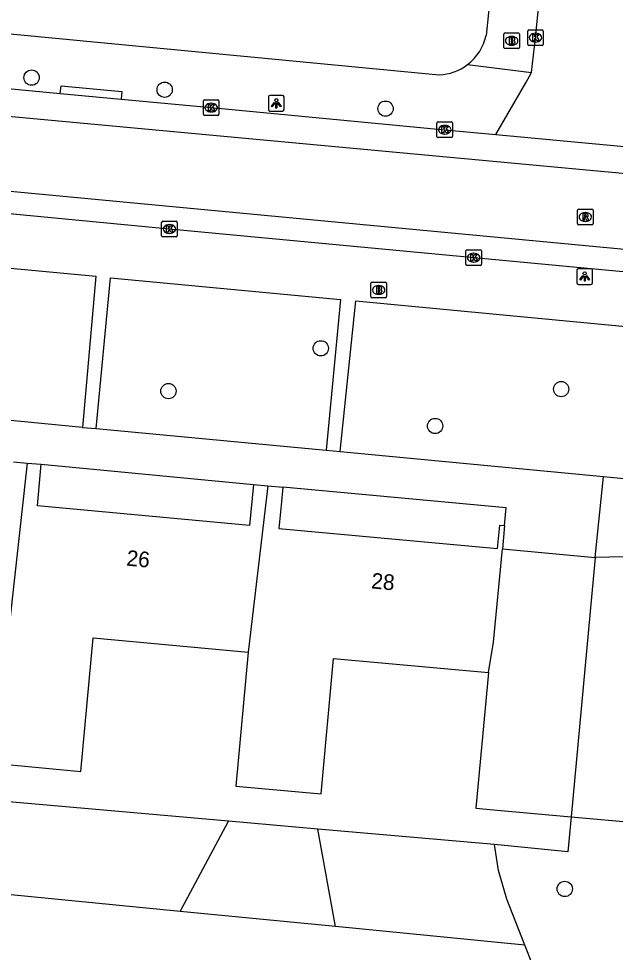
# Model space of a CAD drawing. Extents: x 162186 to 163152, y 385513 to 386513.
# Drawn here: x 162291.8 to 162330, y 385675.7 to 385735.4 of the extents above; entities that cross this region are included whole.
import ezdxf

# ---------------------------------------------------------------- set-up
doc = ezdxf.new("R2010")
doc.units = 0
for name, color, linetype in [('IMGEO_Boom', 7, 'Continuous'), ('IMGEO_Brandkraan', 7, 'Continuous'), ('IMGEO_Groenvoorziening', 7, 'Continuous'), ('IMGEO_Kolk', 7, 'Continuous'), ('IMGEO_Lichtpunt', 7, 'Continuous'), ('IMGEO_Pand', 7, 'Continuous'), ('IMGEO_Pand_nummerreeks', 7, 'Continuous'), ('IMGEO_Rijbaan_lokaal_gesloten', 7, 'Continuous'), ('IMGEO_Rijbaan_lokaal_open', 7, 'Continuous'), ('IMGEO_Rioolput', 7, 'Continuous'), ('IMGEO_Voetpad_open', 7, 'Continuous')]:
    doc.layers.add(name, color=color, linetype=linetype)

msp = doc.modelspace()

# ---------------------------------------------------------------- linework, layer by layer
at = {"layer": 'IMGEO_Boom'}
for centre in [(162292.628, 385731.676), (162301.15, 385730.904), (162315.298, 385729.691), (162311.147, 385714.353), (162326.546, 385711.742), (162301.394, 385711.615), (162318.473, 385709.382), (162326.774, 385679.752)]:
    msp.add_circle(centre, 0.489, dxfattribs=at)
at = {"layer": 'IMGEO_Brandkraan'}
for p, q in [((162322.878, 385733.607), (162322.878, 385734.459)), ((162322.953, 385734.533), (162323.805, 385734.533)), ((162323.366, 385734.313), (162323.391, 385734.313)), ((162323.879, 385734.459), (162323.879, 385733.607)), ((162323.389, 385733.753), (162323.364, 385733.753)), ((162323.805, 385733.533), (162322.953, 385733.533)), ((162314.361, 385717.663), (162314.361, 385718.515)), ((162314.436, 385718.589), (162315.288, 385718.589)), ((162314.849, 385718.369), (162314.874, 385718.369)), ((162315.362, 385718.515), (162315.362, 385717.663)), ((162315.288, 385717.589), (162314.436, 385717.589)), ((162314.872, 385717.809), (162314.847, 385717.809))]:
    msp.add_line(p, q, dxfattribs=at)
for points in [[(162322.878, 385733.607), (162322.878, 385734.459)], [(162322.953, 385734.533), (162323.805, 385734.533)], [(162323.879, 385734.459), (162323.879, 385733.607)], [(162323.226, 385734.233), (162323.226, 385733.833), (162323.439, 385733.833)], [(162323.457, 385734.233), (162323.226, 385734.233)], [(162323.405, 385734.152), (162323.351, 385734.152), (162323.351, 385734.076)], [(162323.351, 385734.076), (162323.404, 385734.076)], [(162323.413, 385734), (162323.351, 385734), (162323.351, 385733.919)], [(162323.351, 385733.919), (162323.413, 385733.919)], [(162323.805, 385733.533), (162322.953, 385733.533)], [(162314.361, 385717.663), (162314.361, 385718.515)], [(162314.436, 385718.589), (162315.288, 385718.589)], [(162314.709, 385718.289), (162314.709, 385717.889), (162314.922, 385717.889)], [(162314.94, 385718.289), (162314.709, 385718.289)], [(162314.888, 385718.208), (162314.834, 385718.208), (162314.834, 385718.132)], [(162315.362, 385718.515), (162315.362, 385717.663)], [(162315.288, 385717.589), (162314.436, 385717.589)], [(162314.834, 385718.132), (162314.887, 385718.132)], [(162314.896, 385718.056), (162314.834, 385718.056), (162314.834, 385717.975)], [(162314.834, 385717.975), (162314.896, 385717.975)]]:
    msp.add_lwpolyline(points, dxfattribs=at)
for centre, radius, start, end in [((162322.955, 385734.457), 0.0765, 91.55205, 178.44795), ((162322.955, 385734.457), 0.0765, 91.55205, 178.44795), ((162323.803, 385734.457), 0.0765, 1.55205, 88.44795), ((162323.803, 385734.457), 0.0765, 1.55205, 88.44795), ((162323.406, 385734.114), 0.0379, 267.82845, 90.93552), ((162323.414, 385733.959), 0.0404, 269.87594, 90.50774), ((162323.445, 385734.084), 0.251, 268.66757, 293.53466), ((162323.461, 385734.088), 0.145, 59.4692, 91.53667), ((162323.486, 385734.135), 0.0922, 285.51372, 58.15012), ((162323.491, 385733.943), 0.105, 301.31148, 78.98903), ((162322.955, 385733.609), 0.0765, 181.55205, 268.44795), ((162322.955, 385733.609), 0.0765, 181.55205, 268.44795), ((162323.803, 385733.609), 0.0765, 271.55205, 358.44795), ((162323.803, 385733.609), 0.0765, 271.55205, 358.44795), ((162314.438, 385718.513), 0.0765, 91.55205, 178.44795), ((162314.438, 385718.513), 0.0765, 91.55205, 178.44795), ((162314.889, 385718.17), 0.0379, 267.82845, 90.93552), ((162314.944, 385718.144), 0.145, 59.4692, 91.53667), ((162314.969, 385718.191), 0.0922, 285.51372, 58.15012), ((162315.286, 385718.513), 0.0765, 1.55205, 88.44795), ((162315.286, 385718.513), 0.0765, 1.55205, 88.44795), ((162314.438, 385717.665), 0.0765, 181.55205, 268.44795), ((162314.438, 385717.665), 0.0765, 181.55205, 268.44795), ((162314.897, 385718.015), 0.0404, 269.87594, 90.50774), ((162314.928, 385718.14), 0.251, 268.66757, 293.53466), ((162314.974, 385717.999), 0.105, 301.31148, 78.98903), ((162315.286, 385717.665), 0.0765, 271.55205, 358.44795), ((162315.286, 385717.665), 0.0765, 271.55205, 358.44795)]:
    msp.add_arc(centre, radius, start, end, dxfattribs=at)
for centre, major_axis, ratio, start_param, end_param in [((162323.365, 385734.033), (-0.387, 0.002), 0.722429, 4.712389, 7.853982), ((162323.39, 385734.033), (-0.39, 0.002), 0.717154, 1.570796, 4.712389), ((162314.848, 385718.089), (-0.387, 0.002), 0.722429, 4.712389, 7.853982), ((162314.873, 385718.089), (-0.39, 0.002), 0.717154, 1.570796, 4.712389)]:
    msp.add_ellipse(centre, major_axis=major_axis, ratio=ratio, start_param=start_param, end_param=end_param, dxfattribs=at)
at = {"layer": 'IMGEO_Groenvoorziening'}
for points in [[(162336.141, 385703.282), (162337.233, 385702.638), (162338.466, 385701.56), (162339.344, 385699.923), (162340.593, 385695.492), (162341.243, 385692.652), (162341.563, 385691.252), (162343.641, 385684.905), (162344.138, 385682.696), (162344.331, 385681.045), (162344.168, 385679.279), (162343.181, 385676.687), (162341.102, 385673.713), (162338.464, 385671.335), (162335.609, 385669.807), (162333.743, 385669.347), (162331.47, 385669.611), (162329.323, 385670.65), (162327.366, 385671.752), (162325.625, 385673.388), (162324.721, 385674.923), (162324.229, 385676.165)], [(162305.235, 385684.094), (162289.198, 385685.507)], [(162302.141, 385678.318), (162305.235, 385684.094)], [(162310.963, 385683.589), (162305.235, 385684.094)], [(162327.188, 385684.362), (162326.973, 385682.13), (162322.266, 385682.593)], [(162312.094, 385677.348), (162310.963, 385683.589)], [(162322.266, 385682.593), (162310.963, 385683.589)], [(162324.229, 385676.165), (162323.066, 385679.099), (162322.53, 385680.94), (162322.266, 385682.593)], [(162302.141, 385678.318), (162289.75, 385679.525)], [(162312.094, 385677.348), (162302.141, 385678.318)], [(162324.229, 385676.165), (162312.094, 385677.348)]]:
    msp.add_lwpolyline(points, dxfattribs=at)
at = {"layer": 'IMGEO_Kolk'}
for p, q in [((162324.403, 385733.806), (162324.403, 385734.658)), ((162324.478, 385734.732), (162325.33, 385734.732)), ((162324.891, 385734.512), (162324.916, 385734.512)), ((162325.404, 385734.658), (162325.404, 385733.806)), ((162325.33, 385733.732), (162324.478, 385733.732)), ((162324.914, 385733.952), (162324.889, 385733.952)), ((162303.629, 385729.334), (162303.629, 385730.186)), ((162303.704, 385730.26), (162304.556, 385730.26)), ((162304.63, 385730.186), (162304.63, 385729.334)), ((162304.117, 385730.04), (162304.142, 385730.04)), ((162304.556, 385729.26), (162303.704, 385729.26)), ((162304.14, 385729.48), (162304.115, 385729.48)), ((162318.592, 385727.914), (162318.592, 385728.766)), ((162318.667, 385728.84), (162319.519, 385728.84)), ((162319.08, 385728.62), (162319.105, 385728.62)), ((162319.593, 385728.766), (162319.593, 385727.914)), ((162319.519, 385727.84), (162318.667, 385727.84)), ((162319.103, 385728.06), (162319.078, 385728.06)), ((162300.957, 385721.561), (162300.957, 385722.413)), ((162301.032, 385722.487), (162301.884, 385722.487)), ((162301.958, 385722.413), (162301.958, 385721.561)), ((162301.445, 385722.267), (162301.47, 385722.267)), ((162301.884, 385721.487), (162301.032, 385721.487)), ((162301.468, 385721.707), (162301.443, 385721.707)), ((162320.441, 385719.729), (162320.441, 385720.581)), ((162320.516, 385720.655), (162321.368, 385720.655)), ((162321.442, 385720.581), (162321.442, 385719.729)), ((162320.929, 385720.435), (162320.954, 385720.435)), ((162321.368, 385719.655), (162320.516, 385719.655)), ((162320.952, 385719.875), (162320.927, 385719.875))]:
    msp.add_line(p, q, dxfattribs=at)
for points in [[(162324.403, 385733.806), (162324.403, 385734.658)], [(162324.478, 385734.732), (162325.33, 385734.732)], [(162324.724, 385734.432), (162324.847, 385734.432), (162324.847, 385734.281), (162324.977, 385734.432), (162325.141, 385734.432), (162324.995, 385734.281), (162325.148, 385734.032), (162324.996, 385734.032), (162324.911, 385734.196), (162324.847, 385734.129), (162324.847, 385734.032), (162324.724, 385734.032), (162324.724, 385734.432)], [(162325.404, 385734.658), (162325.404, 385733.806)], [(162325.33, 385733.732), (162324.478, 385733.732)], [(162303.629, 385729.334), (162303.629, 385730.186)], [(162303.704, 385730.26), (162304.556, 385730.26)], [(162304.63, 385730.186), (162304.63, 385729.334)], [(162303.95, 385729.96), (162304.073, 385729.96), (162304.073, 385729.809), (162304.203, 385729.96), (162304.367, 385729.96), (162304.221, 385729.809), (162304.374, 385729.56), (162304.222, 385729.56), (162304.137, 385729.724), (162304.073, 385729.657), (162304.073, 385729.56), (162303.95, 385729.56), (162303.95, 385729.96)], [(162304.556, 385729.26), (162303.704, 385729.26)], [(162318.592, 385727.914), (162318.592, 385728.766)], [(162318.667, 385728.84), (162319.519, 385728.84)], [(162318.913, 385728.54), (162319.036, 385728.54), (162319.036, 385728.389), (162319.166, 385728.54), (162319.33, 385728.54), (162319.184, 385728.389), (162319.337, 385728.14), (162319.185, 385728.14), (162319.1, 385728.304), (162319.036, 385728.237), (162319.036, 385728.14), (162318.913, 385728.14), (162318.913, 385728.54)], [(162319.593, 385728.766), (162319.593, 385727.914)], [(162319.519, 385727.84), (162318.667, 385727.84)], [(162300.957, 385721.561), (162300.957, 385722.413)], [(162301.032, 385722.487), (162301.884, 385722.487)], [(162301.958, 385722.413), (162301.958, 385721.561)], [(162301.278, 385722.187), (162301.401, 385722.187), (162301.401, 385722.036), (162301.531, 385722.187), (162301.695, 385722.187), (162301.549, 385722.036), (162301.702, 385721.787), (162301.55, 385721.787), (162301.465, 385721.951), (162301.401, 385721.884), (162301.401, 385721.787), (162301.278, 385721.787), (162301.278, 385722.187)], [(162301.884, 385721.487), (162301.032, 385721.487)], [(162320.441, 385719.729), (162320.441, 385720.581)], [(162320.516, 385720.655), (162321.368, 385720.655)], [(162321.442, 385720.581), (162321.442, 385719.729)], [(162320.762, 385720.355), (162320.885, 385720.355), (162320.885, 385720.204), (162321.015, 385720.355), (162321.179, 385720.355), (162321.033, 385720.204), (162321.186, 385719.955), (162321.034, 385719.955), (162320.949, 385720.119), (162320.885, 385720.052), (162320.885, 385719.955), (162320.762, 385719.955), (162320.762, 385720.355)], [(162321.368, 385719.655), (162320.516, 385719.655)]]:
    msp.add_lwpolyline(points, dxfattribs=at)
for centre, start, end in [((162324.48, 385734.656), 91.55205, 178.44795), ((162324.48, 385734.656), 91.55205, 178.44795), ((162325.328, 385734.656), 1.55205, 88.44795), ((162325.328, 385734.656), 1.55205, 88.44795), ((162324.48, 385733.808), 181.55205, 268.44795), ((162324.48, 385733.808), 181.55205, 268.44795), ((162325.328, 385733.808), 271.55205, 358.44795), ((162325.328, 385733.808), 271.55205, 358.44795), ((162303.706, 385730.184), 91.55205, 178.44795), ((162303.706, 385730.184), 91.55205, 178.44795), ((162304.554, 385730.184), 1.55205, 88.44795), ((162304.554, 385730.184), 1.55205, 88.44795), ((162303.706, 385729.336), 181.55205, 268.44795), ((162303.706, 385729.336), 181.55205, 268.44795), ((162304.554, 385729.336), 271.55205, 358.44795), ((162304.554, 385729.336), 271.55205, 358.44795), ((162318.669, 385728.764), 91.55205, 178.44795), ((162318.669, 385728.764), 91.55205, 178.44795), ((162319.517, 385728.764), 1.55205, 88.44795), ((162319.517, 385728.764), 1.55205, 88.44795), ((162318.669, 385727.916), 181.55205, 268.44795), ((162318.669, 385727.916), 181.55205, 268.44795), ((162319.517, 385727.916), 271.55205, 358.44795), ((162319.517, 385727.916), 271.55205, 358.44795), ((162301.034, 385722.411), 91.55205, 178.44795), ((162301.034, 385722.411), 91.55205, 178.44795), ((162301.882, 385722.411), 1.55205, 88.44795), ((162301.882, 385722.411), 1.55205, 88.44795), ((162301.034, 385721.563), 181.55205, 268.44795), ((162301.034, 385721.563), 181.55205, 268.44795), ((162301.882, 385721.563), 271.55205, 358.44795), ((162301.882, 385721.563), 271.55205, 358.44795), ((162320.518, 385720.579), 91.55205, 178.44795), ((162320.518, 385720.579), 91.55205, 178.44795), ((162321.366, 385720.579), 1.55205, 88.44795), ((162321.366, 385720.579), 1.55205, 88.44795), ((162320.518, 385719.731), 181.55205, 268.44795), ((162320.518, 385719.731), 181.55205, 268.44795), ((162321.366, 385719.731), 271.55205, 358.44795), ((162321.366, 385719.731), 271.55205, 358.44795)]:
    msp.add_arc(centre, 0.0765, start, end, dxfattribs=at)
for centre, major_axis, ratio, start_param, end_param in [((162324.89, 385734.232), (-0.387, 0.002), 0.722429, 4.712389, 7.853982), ((162324.915, 385734.232), (-0.39, 0.002), 0.717154, 1.570796, 4.712389), ((162304.116, 385729.76), (-0.387, 0.002), 0.722429, 4.712389, 7.853982), ((162304.141, 385729.76), (-0.39, 0.002), 0.717154, 1.570796, 4.712389), ((162319.079, 385728.34), (-0.387, 0.002), 0.722429, 4.712389, 7.853982), ((162319.104, 385728.34), (-0.39, 0.002), 0.717154, 1.570796, 4.712389), ((162301.444, 385721.987), (-0.387, 0.002), 0.722429, 4.712389, 7.853982), ((162301.469, 385721.987), (-0.39, 0.002), 0.717154, 1.570796, 4.712389), ((162320.928, 385720.155), (-0.387, 0.002), 0.722429, 4.712389, 7.853982), ((162320.953, 385720.155), (-0.39, 0.002), 0.717154, 1.570796, 4.712389)]:
    msp.add_ellipse(centre, major_axis=major_axis, ratio=ratio, start_param=start_param, end_param=end_param, dxfattribs=at)
at = {"layer": 'IMGEO_Lichtpunt'}
for p, q in [((162307.802, 385730.437), (162307.802, 385729.63)), ((162307.802, 385730.437), (162307.802, 385729.63)), ((162308.704, 385730.532), (162307.896, 385730.532)), ((162308.704, 385730.532), (162307.896, 385730.532)), ((162308.798, 385729.63), (162308.798, 385730.437)), ((162308.798, 385729.63), (162308.798, 385730.437)), ((162307.896, 385729.536), (162308.704, 385729.536)), ((162307.896, 385729.536), (162308.704, 385729.536)), ((162327.555, 385719.348), (162327.555, 385718.541)), ((162327.555, 385719.348), (162327.555, 385718.541)), ((162328.457, 385719.443), (162327.649, 385719.443)), ((162328.457, 385719.443), (162327.649, 385719.443)), ((162328.551, 385718.541), (162328.551, 385719.348)), ((162328.551, 385718.541), (162328.551, 385719.348)), ((162327.649, 385718.447), (162328.457, 385718.447)), ((162327.649, 385718.447), (162328.457, 385718.447))]:
    msp.add_line(p, q, dxfattribs=at)
for points in [[(162308.176, 385730.101), (162308.215, 385730.073), (162308.027, 385729.811), (162307.989, 385729.838), (162308.176, 385730.101)], [(162308.388, 385730.073), (162308.426, 385730.1), (162308.613, 385729.838), (162308.574, 385729.81), (162308.388, 385730.073)], [(162308.278, 385730.053), (162308.325, 385730.053), (162308.325, 385729.731), (162308.278, 385729.731), (162308.278, 385730.053)], [(162327.929, 385719.012), (162327.968, 385718.984), (162327.78, 385718.722), (162327.742, 385718.749), (162327.929, 385719.012)], [(162328.031, 385718.964), (162328.078, 385718.964), (162328.078, 385718.642), (162328.031, 385718.642), (162328.031, 385718.964)], [(162328.141, 385718.984), (162328.179, 385719.011), (162328.366, 385718.749), (162328.327, 385718.721), (162328.141, 385718.984)]]:
    msp.add_lwpolyline(points, dxfattribs=at)
for centre in [(162308.301, 385730.235), (162328.054, 385719.146)]:
    msp.add_circle(centre, 0.0994, dxfattribs=at)
for centre, start, end in [((162307.896, 385730.437), 90, 180), ((162307.896, 385730.437), 90, 180), ((162308.704, 385730.437), 0, 90), ((162308.704, 385730.437), 0, 90), ((162307.896, 385729.63), 180, 270), ((162307.896, 385729.63), 180, 270), ((162308.704, 385729.63), 270, 0), ((162308.704, 385729.63), 270, 360), ((162327.649, 385719.348), 90, 180), ((162327.649, 385719.348), 90, 180), ((162328.457, 385719.348), 0, 90), ((162328.457, 385719.348), 0, 90), ((162327.649, 385718.541), 180, 270), ((162327.649, 385718.541), 180, 270), ((162328.457, 385718.541), 270, 0), ((162328.457, 385718.541), 270, 360)]:
    msp.add_arc(centre, 0.0946, start, end, dxfattribs=at)
at = {"layer": 'IMGEO_Pand'}
for points in [[(162292.352, 385707.012), (162291.172, 385696.37)], [(162291.458, 385707.094), (162292.352, 385707.012)], [(162292.352, 385707.012), (162293.244, 385706.93)], [(162306.832, 385705.633), (162306.592, 385703.015), (162292.999, 385704.264), (162293.244, 385706.93)], [(162306.832, 385705.633), (162307.769, 385705.547)], [(162307.769, 385705.547), (162306.491, 385694.912)], [(162307.769, 385705.547), (162308.709, 385705.461)], [(162308.709, 385705.461), (162308.604, 385704.321), (162308.467, 385702.826), (162322.475, 385701.539), (162322.612, 385703.033), (162322.918, 385703.005)], [(162322.918, 385703.005), (162322.781, 385701.517)], [(162321.883, 385693.597), (162322.206, 385695.549), (162322.781, 385701.517)], [(162322.781, 385701.517), (162328.715, 385700.972)], [(162328.715, 385700.972), (162327.188, 385684.362)], [(162291.172, 385696.37), (162290.382, 385687.776), (162295.779, 385687.28), (162296.563, 385695.824), (162306.491, 385694.912)], [(162306.491, 385694.912), (162305.703, 385686.338), (162311.169, 385685.835), (162311.965, 385694.508), (162321.883, 385693.597)], [(162321.883, 385693.597), (162321.086, 385684.923), (162322.209, 385684.82), (162327.188, 385684.362)]]:
    msp.add_lwpolyline(points, dxfattribs=at)
at = {"layer": 'IMGEO_Rijbaan_lokaal_gesloten'}
for points in [[(162448.032, 385717.26), (162447.815, 385715.531), (162435.147, 385716.798), (162424.505, 385717.305), (162408.881, 385718.15), (162367.51, 385722.111), (162286.519, 385729.622), (162260.4, 385732.301)], [(162278.838, 385732.156), (162282.654, 385731.794), (162294.467, 385730.661)], [(162294.467, 385730.661), (162298.361, 385730.297)], [(162298.361, 385730.297), (162304.126, 385729.759), (162319.089, 385728.339), (162322.366, 385728.035)], [(162322.366, 385728.035), (162333.341, 385727.013)], [(162259.916, 385727.292), (162279.939, 385725.485), (162345.976, 385719.242), (162380.728, 385715.866), (162402.855, 385713.753), (162412.106, 385712.917), (162421.565, 385711.819), (162434.403, 385709.622), (162446.455, 385707.767), (162446.191, 385706.141)], [(162333.913, 385718.934), (162301.454, 385721.988), (162282.94, 385723.756), (162268.178, 385725.161), (162263.448, 385725.604), (162259.786, 385725.953)]]:
    msp.add_lwpolyline(points, dxfattribs=at)
at = {"layer": 'IMGEO_Rijbaan_lokaal_open'}
for points in [[(162324.656, 385731.996), (162324.906, 385734.232), (162326.477, 385750), (162326.635, 385751.709)], [(162322.366, 385728.035), (162324.274, 385731.336), (162324.656, 385731.996)], [(162327.188, 385684.362), (162334.344, 385683.735), (162336.141, 385703.282)], [(162331.465, 385701.032), (162328.715, 385700.972)]]:
    msp.add_lwpolyline(points, dxfattribs=at)
at = {"layer": 'IMGEO_Rioolput'}
for p, q in [((162327.59, 385722.333), (162327.59, 385723.185)), ((162327.665, 385723.259), (162328.517, 385723.259)), ((162328.078, 385723.039), (162328.103, 385723.039)), ((162328.591, 385723.185), (162328.591, 385722.333)), ((162328.101, 385722.479), (162328.076, 385722.479)), ((162328.517, 385722.259), (162327.665, 385722.259))]:
    msp.add_line(p, q, dxfattribs=at)
for points in [[(162327.59, 385722.333), (162327.59, 385723.185)], [(162327.665, 385723.259), (162328.517, 385723.259)], [(162328.179, 385722.957), (162327.927, 385722.959), (162327.927, 385722.559)], [(162328.591, 385723.185), (162328.591, 385722.333)], [(162327.927, 385722.559), (162328.051, 385722.559), (162328.051, 385722.721), (162328.062, 385722.721)], [(162328.105, 385722.878), (162328.051, 385722.878), (162328.051, 385722.797)], [(162328.051, 385722.797), (162328.103, 385722.797)], [(162328.109, 385722.692), (162328.18, 385722.559), (162328.32, 385722.559), (162328.255, 385722.685)], [(162328.517, 385722.259), (162327.665, 385722.259)]]:
    msp.add_lwpolyline(points, dxfattribs=at)
for centre, radius, start, end in [((162327.667, 385723.183), 0.0765, 91.55205, 178.44795), ((162327.667, 385723.183), 0.0765, 91.55205, 178.44795), ((162328.178, 385722.847), 0.109, 350.36119, 89.41601), ((162328.515, 385723.183), 0.0765, 1.55205, 88.44795), ((162328.515, 385723.183), 0.0765, 1.55205, 88.44795), ((162327.667, 385722.335), 0.0765, 181.55205, 268.44795), ((162327.667, 385722.335), 0.0765, 181.55205, 268.44795), ((162328.061, 385722.668), 0.0533, 26.02933, 88.69889), ((162328.087, 385722.986), 0.19, 274.7715, 282.96867), ((162328.111, 385722.782), 0.0964, 77.00612, 93.18647), ((162328.125, 385722.839), 0.0378, 276.66336, 79.67722), ((162328.176, 385722.847), 0.112, 277.58423, 350.98172), ((162328.16, 385722.632), 0.108, 29.51342, 73.79051), ((162328.515, 385722.335), 0.0765, 271.55205, 358.44795), ((162328.515, 385722.335), 0.0765, 271.55205, 358.44795)]:
    msp.add_arc(centre, radius, start, end, dxfattribs=at)
for centre, major_axis, ratio, start_param, end_param in [((162328.077, 385722.759), (-0.387, 0.002), 0.722429, 4.712389, 7.853982), ((162328.102, 385722.759), (-0.39, 0.002), 0.717154, 1.570796, 4.712389)]:
    msp.add_ellipse(centre, major_axis=major_axis, ratio=ratio, start_param=start_param, end_param=end_param, dxfattribs=at)
at = {"layer": 'IMGEO_Voetpad_open'}
for points in [[(162407.363, 385803.678), (162329.194, 385811.19), (162323.482, 385750), (162322.185, 385738.742), (162321.743, 385734.363)], [(162259.069, 385737.577), (162318.739, 385731.852)], [(162320.551, 385732.517), (162324.656, 385731.996)], [(162294.467, 385730.661), (162294.513, 385731.158), (162298.407, 385730.795), (162298.361, 385730.297)], [(162281.877, 385715.117), (162282.373, 385720.324), (162296.749, 385718.963), (162295.879, 385709.284)], [(162296.769, 385709.213), (162297.691, 385718.874), (162312.412, 385717.479), (162311.499, 385707.842)], [(162312.393, 385707.757), (162313.385, 385717.388), (162314.067, 385717.323), (162334.297, 385715.407)], [(162295.879, 385709.284), (162290.842, 385709.783)], [(162295.879, 385709.284), (162296.769, 385709.213)], [(162296.769, 385709.213), (162311.499, 385707.842)], [(162311.499, 385707.842), (162312.393, 385707.757)], [(162312.393, 385707.757), (162329.258, 385706.149)], [(162293.244, 385706.93), (162306.832, 385705.633)], [(162328.715, 385700.972), (162329.258, 385706.149)], [(162329.258, 385706.149), (162333.232, 385705.772), (162333.385, 385705.758)], [(162322.918, 385703.005), (162323.024, 385704.151), (162308.709, 385705.461)]]:
    msp.add_lwpolyline(points, dxfattribs=at)
for centre, radius, start, end in [((162318.582, 385735.096), 3.245, 307.35746, 346.94023), ((162318.574, 385735.104), 3.256, 272.91211, 307.39394)]:
    msp.add_arc(centre, radius, start, end, dxfattribs=at)

# ---------------------------------------------------------------- texts
at = {"layer": 'IMGEO_Pand_nummerreeks'}
for s, rotation, p in [('26', 354.75009, (162298.673, 385700.45)), ('28', 354.75062, (162314.352, 385698.992))]:
    msp.add_text(s, height=1, rotation=rotation, dxfattribs=at).set_placement(p)

doc.saveas('drawing.dxf')
